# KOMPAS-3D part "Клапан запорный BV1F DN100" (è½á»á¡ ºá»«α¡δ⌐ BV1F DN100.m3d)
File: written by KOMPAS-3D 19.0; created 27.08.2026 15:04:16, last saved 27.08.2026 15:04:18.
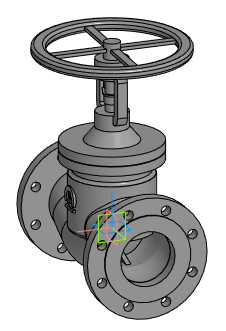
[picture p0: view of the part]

Document properties: Автор: Энергия; Полное имя файла: E:\Dendor\_3D для проектировщиков\5.6 Клапан запорный BV1F\stp\Клапан запорный BV1F DN100.m3d

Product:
- Part/product: Клапан запорный BV1F DN100
    Масса: 49.7328

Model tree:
1. Операция без истории:1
